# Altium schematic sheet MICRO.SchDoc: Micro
size 419 x 266 mm; Date: May 24, 2007; DrawnBy: Yossi Har-Nov; Engineer: Yossi Har-Nov; Revision: 1.0; SheetNumber: 2; SheetTotal: 3; PageSetup: Record=PageOptions|CenterHorizontal=True|CenterVertical=True|PrintScale=0.66|XCorrection=1.00|YCorrection=1.00|PrintKind=1|BorderSize=5000000|LeftOffset=0|BottomOffset=0|Orientation=2|PaperLength=2794|PaperWidth=2159|Scale=100|PaperSource=7|PrintQuality=600|MediaType=1|DitherType=2|PaperKind=Letter|PrintScaleMode=1
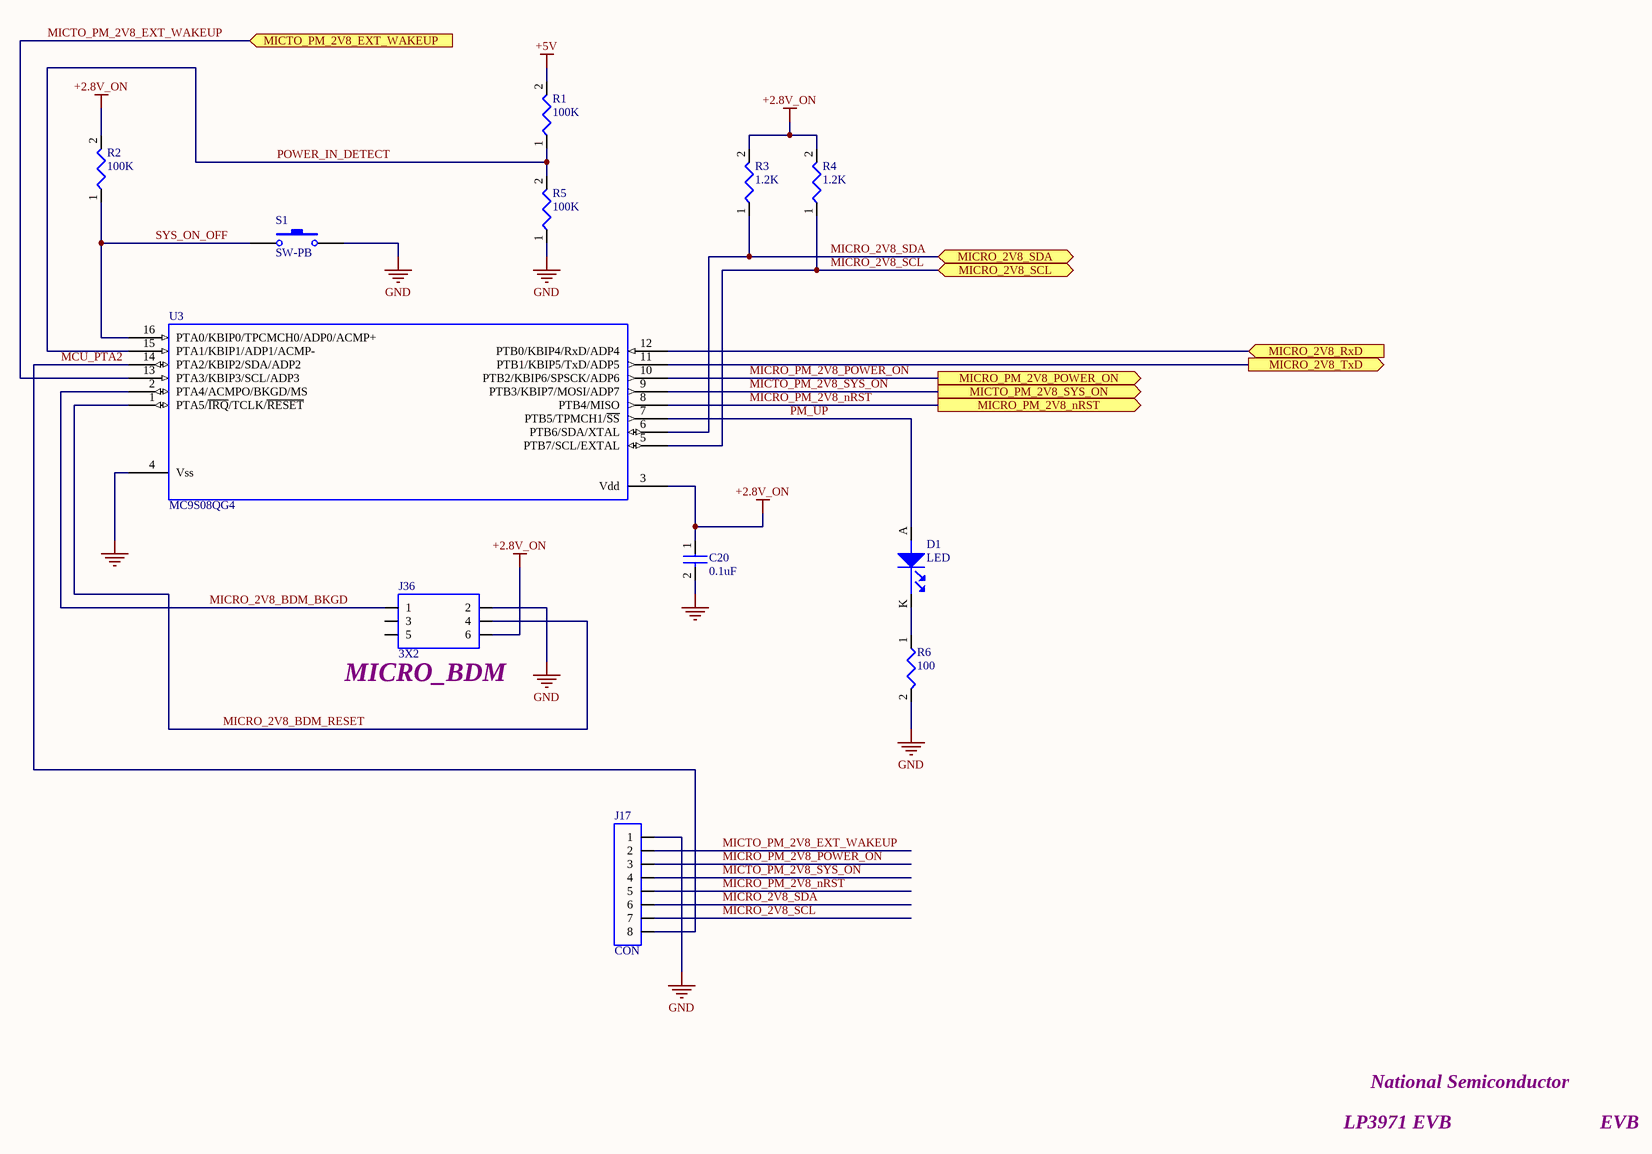
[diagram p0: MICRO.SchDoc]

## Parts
C20  0.1uF  [0603_C]
D1  LED  [0603_LED]
J17  CON  [BH8-NP]
J36  3X2  [HEADER_BOX_3X2]
R1  100K  [0603_R]
R2  100K  [0603_R]
R3  1.2K  [0603_R]
R4  1.2K  [0603_R]
R5  100K  [0603_R]
R6  100  [0603_R]
S1  SW-PB  [B3F-602X]
U3  MC9S08QG4  [TSSOP_16]

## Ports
MICRO_2V8_RxD (in), MICRO_2V8_SCL (bidir), MICRO_2V8_SDA (bidir), MICRO_2V8_TxD (out), MICRO_PM_2V8_nRST (out), MICRO_PM_2V8_POWER_ON (out), MICTO_PM_2V8_EXT_WAKEUP (in), MICTO_PM_2V8_SYS_ON (out)

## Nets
+2.8V_ON: C20.1 J36.6 R2.2 R3.2 R4.2 U3.3(Vdd)
+5V: R1.2
GND: C20.2 J17.1 J36.2 R5.1 R6.2 S1.2 U3.4(Vss)
MCU_PTA2: J17.8 U3.14(PTA2/KBIP2/SDA/ADP2)
MICRO_2V8_BDM_BKGD: J36.1 U3.2(PTA4/ACMPO/BKGD/MS)
MICRO_2V8_BDM_RESET: J36.4 U3.1(PTA5/~{IRQ}/TCLK/~{RESET})
MICRO_2V8_RxD: U3.12(PTB0/KBIP4/RxD/ADP4) ; port MICRO_2V8_RxD
MICRO_2V8_SCL: J17.7 R4.1 U3.5(PTB7/SCL/EXTAL) ; port MICRO_2V8_SCL
MICRO_2V8_SDA: J17.6 R3.1 U3.6(PTB6/SDA/XTAL) ; port MICRO_2V8_SDA
MICRO_2V8_TxD: U3.11(PTB1/KBIP5/TxD/ADP5) ; port MICRO_2V8_TxD
MICRO_PM_2V8_nRST: J17.5 U3.8(PTB4/MISO) ; port MICRO_PM_2V8_nRST
MICRO_PM_2V8_POWER_ON: J17.3 U3.10(PTB2/KBIP6/SPSCK/ADP6) ; port MICRO_PM_2V8_POWER_ON
MICTO_PM_2V8_EXT_WAKEUP: J17.2 U3.13(PTA3/KBIP3/SCL/ADP3) ; port MICTO_PM_2V8_EXT_WAKEUP
MICTO_PM_2V8_SYS_ON: J17.4 U3.9(PTB3/KBIP7/MOSI/ADP7) ; port MICTO_PM_2V8_SYS_ON
PM_UP: D1.A U3.7(PTB5/TPMCH1/~{SS})
POWER_IN_DETECT: R1.1 R5.2 U3.15(PTA1/KBIP1/ADP1/ACMP-)
SYS_ON_OFF: R2.1 S1.1 U3.16(PTA0/KBIP0/TPCMCH0/ADP0/ACMP+)
NetD1_K: D1.K R6.1

Not connected (* = marked no-connect by the designer): J36 3 5

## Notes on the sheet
- (near J36) MICRO_BDM
- National Semiconductor
- LP3971 EVB
- EVB

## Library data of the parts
C20 = CAP_0603: Capasitor 0603footprint; Right: 20; Bottom: 10; STUFF: Option - Motion Control
J17 = CON8: Right: 20; Bottom: 50
J36 = HEADER_3X2
R1-R5 = RESISOTR 0603: Resistor 0603 footprint; STUFF: Option - Motion Control
R6 = RESISOTR 0603: Resistor 0603 footprint
S1 = SW-PB: Switch; PART: B3F6002BYOMZ; OMRON: MFG
U3 = MC9S08QG4CDT: 8 bit MCU from FreeScale; STUFF: Option - Motion Control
